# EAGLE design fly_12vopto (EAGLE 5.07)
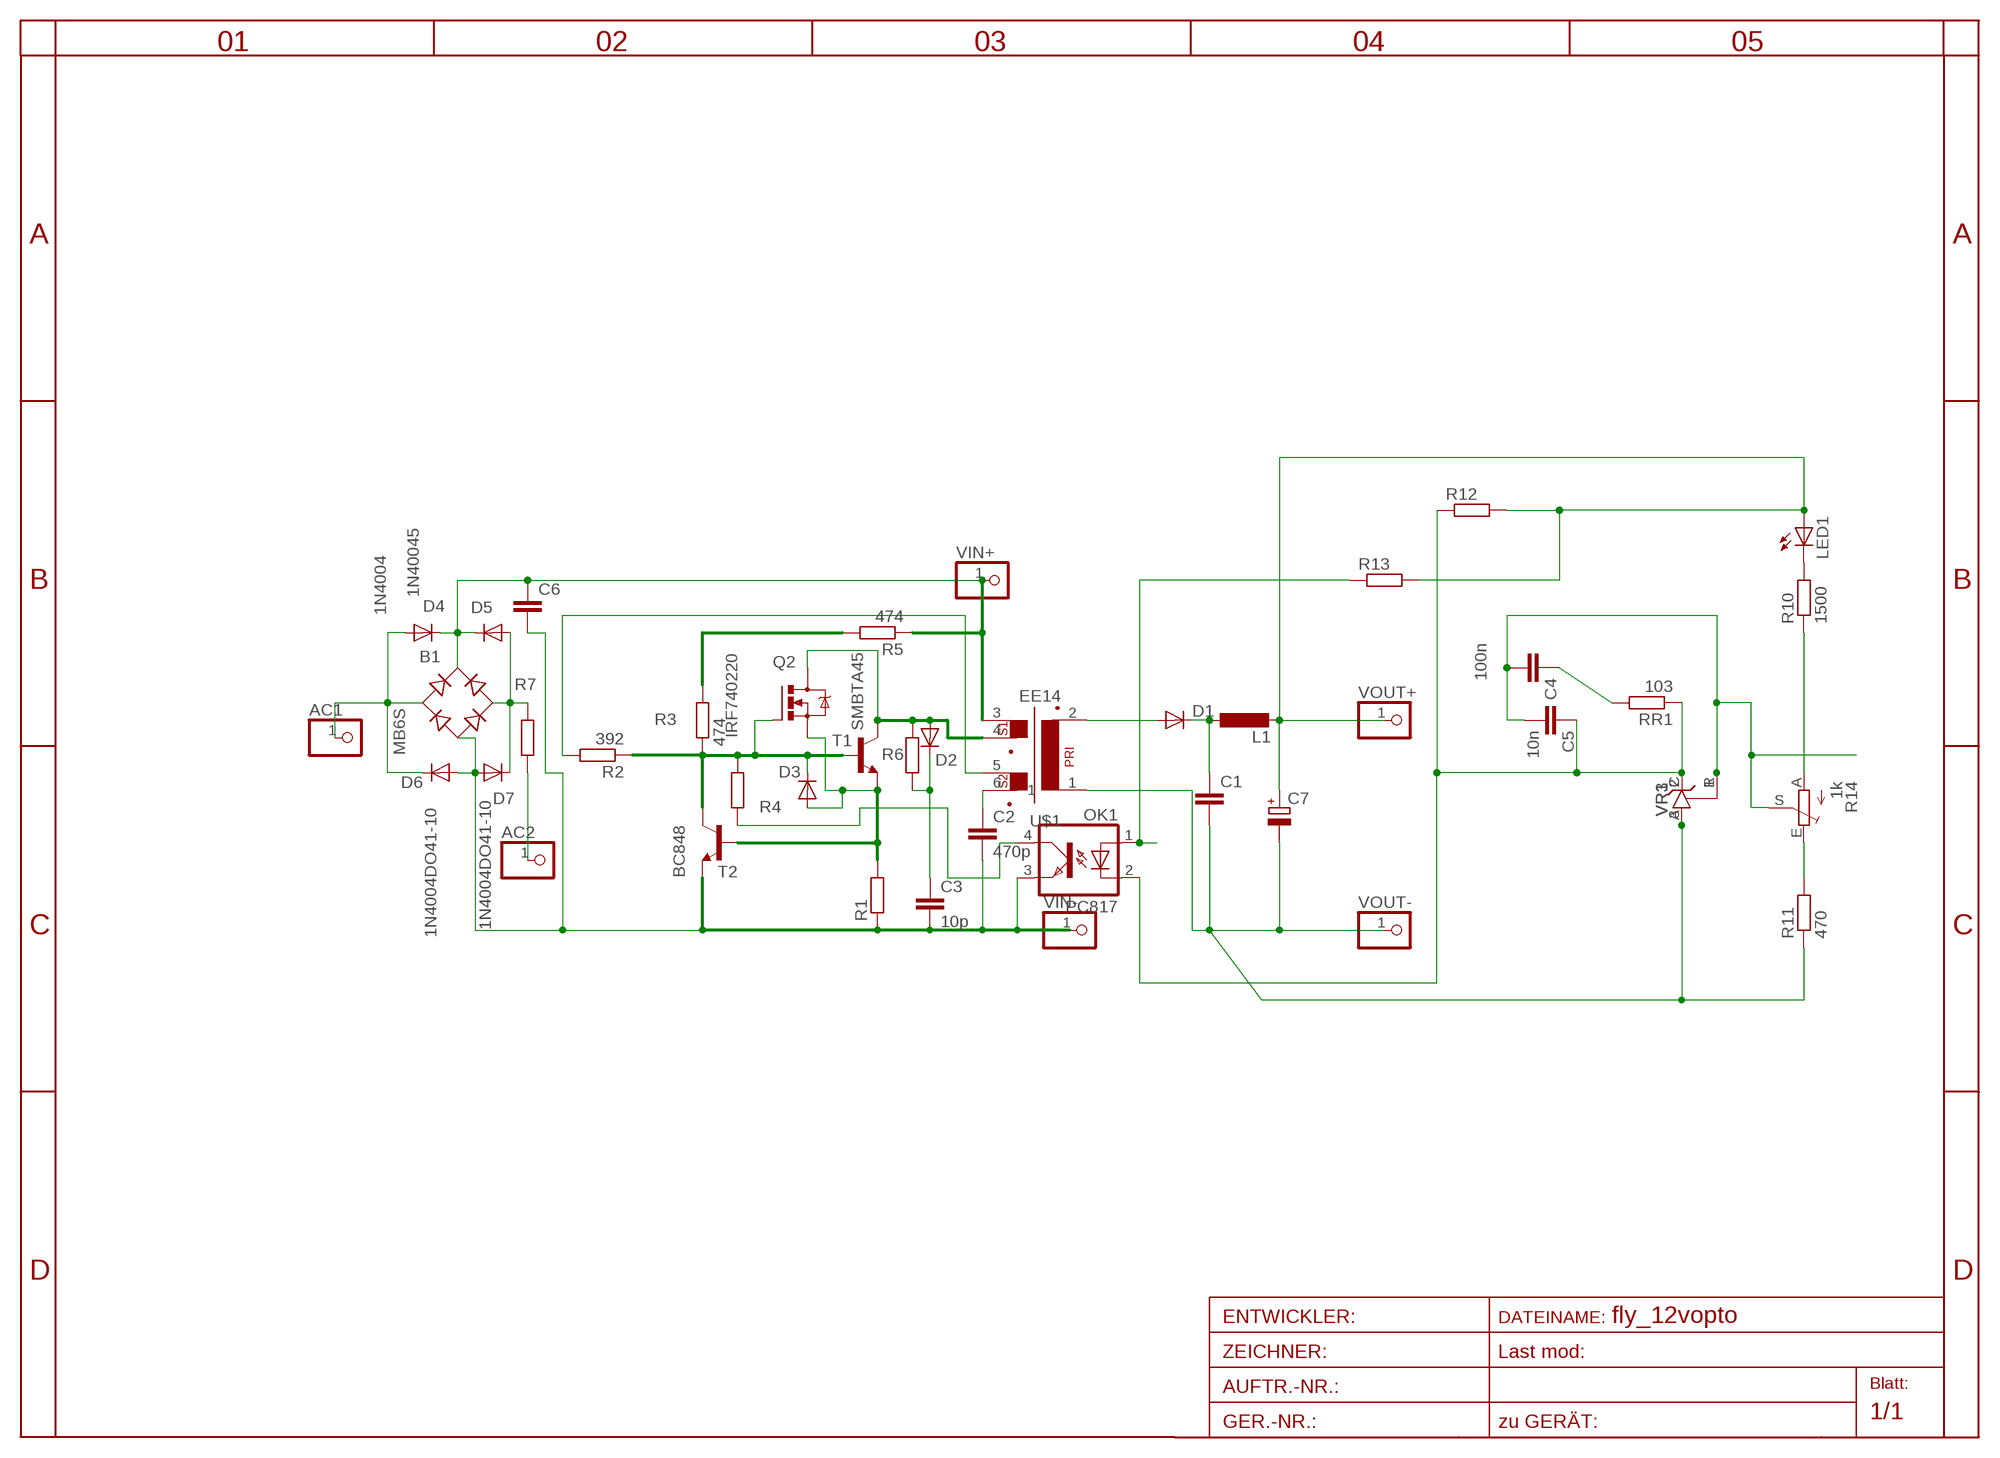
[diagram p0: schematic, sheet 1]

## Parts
AC1  PINHD-1X11MM6  [1X1MM8]
AC2  PINHD-1X11MM6  [1X1MM8]
B1  MB6S  [SOIC-4]
C1  C-EUC0805  [C0805]
C2  470p  C-EUC0805  [C0805]
C3  10p  C-EU050-025X075  [C050-025X075]
C4  100n  C-EUC0805  [C0805]
C5  10n  C-EUC0805  [C0805]
C6  C-EU050-025X075  [C050-025X075]
C7  CPOL-EUE2.5-7  [E2,5-7]
D1  DIODE-SMA-DO214  [SMA-DO214AC]
D2  DIODE-D-5  [D-5]
D3  DIODE-MINIMELF  [MINIMELF]
D4  1N4004  [D-7.5]
D5  1N40045  [C1702-05]
D6  1N4004DO41-10  [DO41-10]
D7  1N4004DO41-10  [DO41-10]
L1  L-EU0204V  [0204V]
LED1  LED3MM  [LED3MM]
OK1  PC817  [DIL04]
Q2  IRF740220  [TO220BV]
R1  R-EU_0204/3  [0204/3]
R2  392  R-EU_R0805  [R0805]
R3  474  R-EU_R1206  [R1206]
R4  R-EU_R0805  [R0805]
R5  474  R-EU_R1206  [R1206]
R6  R-EU_0204/5  [0204/5]
R7  R-EU_0204/3  [0204/3]
R10  1500  R-EU_R0805  [R0805]
R11  470  R-EU_R1206  [R1206]
R12  R-EU_R0805  [R0805]
R13  R-EU_R0805  [R0805]
R14  1k  TRIM_EU-S64W  [S64W]
RR1  103  R-EU_R0805  [R0805]
T1  SMBTA45  BC848  [SOT23]
T2  BC848  [SOT23]
U$1  EE14  EE14EE20G  [EE20GREEN]
VIN+  PINHD-1X11MM6  [1X1MM8]
VIN-  PINHD-1X11MM6  [1X1MM8]
VOUT+  PINHD-1X11MM6  [1X1MM8]
VOUT-  PINHD-1X11MM6  [1X1MM8]
VR1  TL431CLPSOT23  [SOT23]
VR3  TL431CLPTO  [TO92-CLP]

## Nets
A: R10.1 R14.A
AC1: AC1.1 B1.~1(AC1) D4.A D6.C
AC2: AC2.1 R7.1
AC3: B1.~2(AC2) D5.A D7.C R7.2
B1C2: D3.C Q2.G R2.1 R3.1 R4.2 T1.B T2.C
C1: D2.A Q2.D R6.2 T1.C U$1.4
E: R11.2 R14.E
EB: D3.A Q2.S R1.2 T1.E T2.B
K9: C1.1 D1.K(C) L1.1
L3DOT: D1.A U$1.2
N$1: R3.2 R5.2
N$2: R2.2 U$1.5
N$3: C2.1 U$1.6
N$4: LED1.K(C) R10.2
N$5: OK1.4(COL) R4.1
N$6: C3.1 D2.C R6.1
N$7: C5.1 OK1.2(C) R12.1 RR1.1 VR1.2(C) VR3.C
N$8: OK1.1(A) R13.1
N$13: C4.1 RR1.2
OUTMINUS: C1.2 C7.- R11.1 U$1.1 VOUT-.1 VR1.3(A) VR3.A
S: C4.2 C5.2 R14.S VR1.1(R) VR3.R
V+: B1.+ C6.1 D4.C D5.C R5.1 U$1.3 VIN+.1
V-: B1.- C2.2 C3.2 C6.2 D6.A D7.A OK1.3(EMIT) R1.1 T2.E VIN-.1
VOUT+: C7.+ L1.2 LED1.A R12.2 R13.2 VOUT+.1

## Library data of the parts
AC1 AC2 VIN+ VIN- VOUT+ VOUT- = pinhead:PINHD-1X1: PIN HEADER
B1 = rectifier:MB*S: Bridge Rectifier Source: http://www.fairchildsemi.com/ds/MB/MB6S.pdf
C1-C6 = rcl:C-EU: CAPACITOR, European symbol
C7 = rcl:CPOL-EU: POLARIZED CAPACITOR, European symbol
D1-D3 = diode:DIODE-: DIODE
D4-D7 = diode:1N4004: DIODE
L1 = rcl:L-EU: INDUCTOR, European symbol
LED1 = led:LED: LED
OK1 = optocoupler:PC817: SHARP OPTO COUPLER
Q2 = transistor-power:IRF740: N-CHANNEL MOS FET
R1-R7 R10-R13 RR1 = rcl:R-EU_: RESISTOR, European symbol
R14 = pot:TRIM_EU-: POTENTIOMETER
T1 T2 = transistor:BC848: NPN TRANSISTOR
U$1 = trafo:EE14
VR1 VR3 = v-reg:TL431CLP: VOLTAGE REGULATOR

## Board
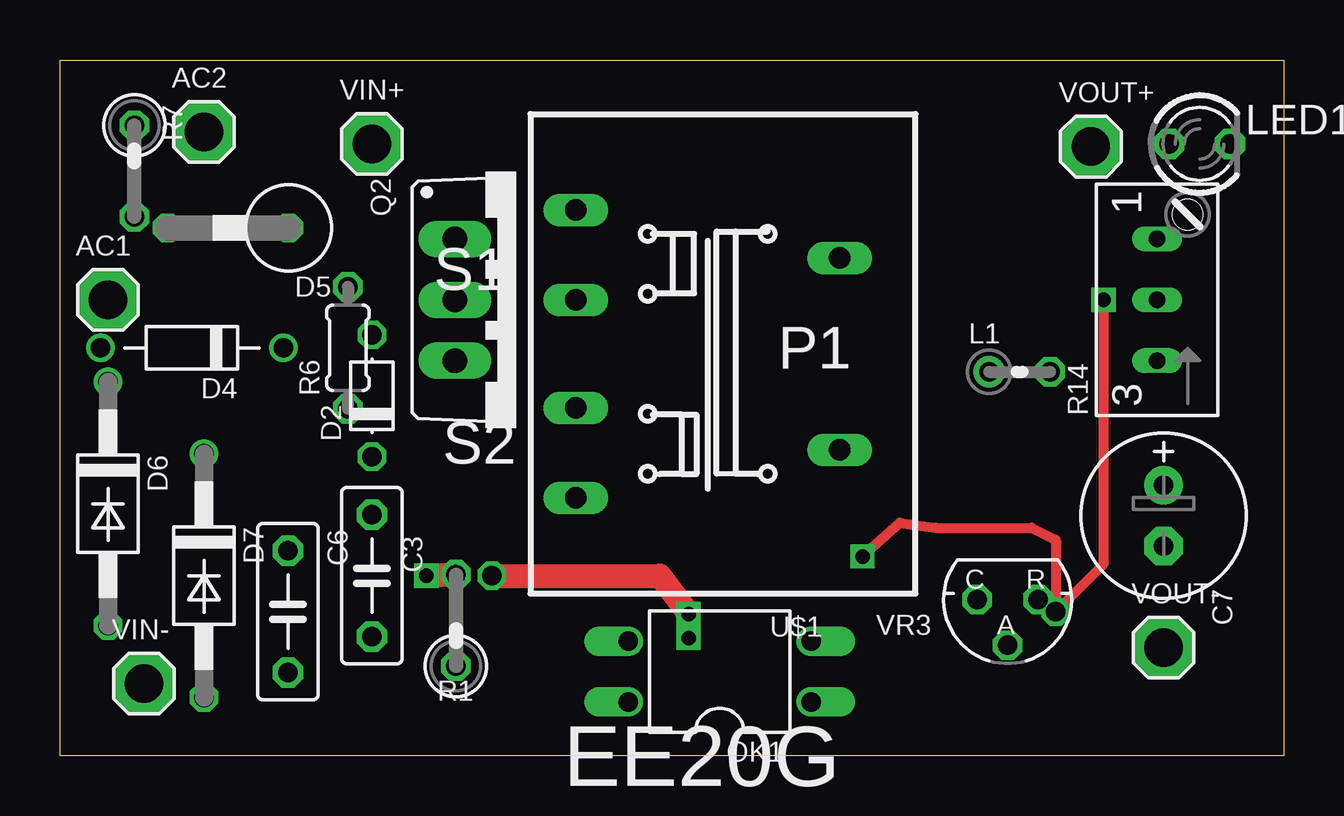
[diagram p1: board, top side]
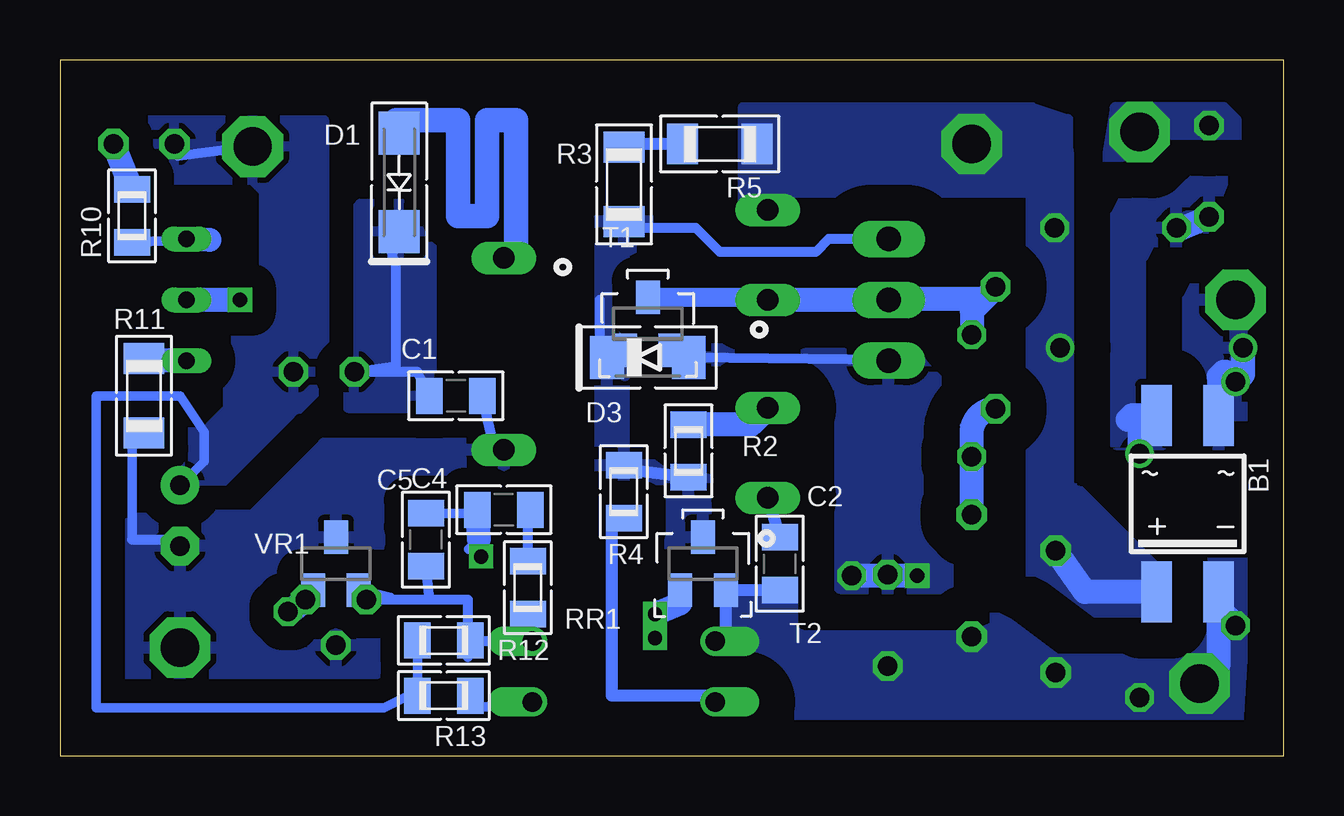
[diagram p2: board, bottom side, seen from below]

Size 51 x 29 mm. Coordinates in mm from the lower left corner, seen from the top.
Outline: 0,29 51,29 51,0 0,0 0,29
Copper layers (1*16): Top 0.035mm / dielectric 1.5mm / Bottom 0.035mm
Design rules "default *": minimum track width 10mil, minimum drill 20mil, track to track 8mil, track to pad 8mil, pad to pad 8mil, via to via 8mil, smd to smd 8mil, copper to edge 40mil, drill to drill 8mil, minimum pad ring 5mil, minimum via ring 8mil, stop-mask expansion 4mil, vias tented up to drill 0mil, thermal gap 10mil

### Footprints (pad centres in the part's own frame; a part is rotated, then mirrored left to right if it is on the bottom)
1X1MM8 = drill 1.6 pad 2.54 octagon: 1 0,0
SOIC-4 = smd 1.27 x 2.54: + 1.3,3.685; - -1.3,3.685; ~1 -1.3,-3.685; ~2 1.3,-3.685
C0805 = smd 1.1 x 1.5: 1 -1.1,0; 2 1.1,0
C050-025X075 = drill 0.8 pad 1.27 octagon: 1 -2.54,0; 2 2.54,0
E2,5-7 = drill 0.813 pad 1.6 round: + -1.27,0 | drill 0.813 pad 1.6 octagon: - 1.27,0
SMA-DO214AC = smd 1.8 x 1.7: A 2.05,-0.127; K -2.05,-0.127
D-5 = drill 0.8 octagon: A 2.54,0; C -2.54,0
MINIMELF = smd 1.4 x 1.8: A 1.7,0; C -1.7,0
D-7.5 = drill 0.8 round: A 3.81,0; C -3.81,0
C1702-05 = drill 0.8 octagon: A 2.54,0; C -2.54,0
DO41-10 = drill 0.8 octagon: A 5.08,0 | drill 0.8 round: C -5.08,0
0204V = drill 0.813 octagon: 1 -1.27,0; 2 1.27,0
LED3MM = drill 0.8 pad 1.27 octagon: A -1.27,0; K 1.27,0
DIL04 = drill 0.813 offset: 1 -1.27,-3.81; 2 1.27,-3.81; 3 1.27,3.81; 4 -1.27,3.81
TO220BV = drill 1.016 long: D 0,-2.54; G -2.54,-2.54; S 2.54,-2.54
0204/3 = drill 0.813 octagon: 1 -1.27,0; 2 2.54,0
R0805 = smd 1.1 x 1.5: 1 -1.1,0; 2 1.1,0
R1206 = smd 1.3 x 1.7: 1 -1.55,0; 2 1.55,0
0204/5 = drill 0.813 octagon: 1 -2.54,0; 2 2.54,0
S64W = drill 0.7 long: A 2.54,1.27; E -2.54,1.27; S 0,1.27
SOT23 = smd 1 x 1.4: B -0.95,-1.1; C 0,1.1; E 0.95,-1.1
EE20GREEN = drill 0.9 pad 1.2 long: 1 5.5,-4; 2 5.5,4; 3 -5.5,6; 4 -5.5,2.25; 5 -5.5,-2.25; 6 -5.5,-6
SOT23' = smd 1 x 1.4: 1 -0.95,-1.1; 2 0.95,-1.1; 3 0,1.1
TO92-CLP = drill 0.813 octagon: A 0,1.905; C 1.27,0; R -1.27,0

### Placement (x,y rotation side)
AC1  2,19 0 top
AC2  6,26 0 top
B1  4,10.5 180 bottom
C1  34.5,15 0 bottom
C2  21,8 270 bottom
C3  13,7.5 270 top
C4  32.5,10.25 180 bottom
C5  35.75,9 90 bottom
C6  9.5,6 270 top
C7  46,10 270 top
D1  36.99,23.89 90 bottom
D2  13,15 90 top
D3  26.5,16.6 0 bottom
D4  5.5,17 180 top
D5  7,22 180 top
D6  2,10.5 270 top
D7  6,7.5 270 top
L1  40,16 0 top
LED1  47.5,25.5 0 top
OK1  27.5,3.5 90 top
Q2  19,19 270 top
R1  16.5,5 90 top
R2  24.8,12.7 90 bottom
R3  27.49,23.81 90 bottom
R4  27.5,11 90 bottom
R5  23.5,25.5 180 bottom
R6  12,17 90 top
R7  3.1,25 270 top
R10  48,22.5 90 bottom
R11  47.5,15 90 bottom
R12  35,4.8 180 bottom
R13  35,2.5 180 bottom
R14  47,19 90 top
RR1  31.5,7 90 bottom
T1  26.5,18 0 bottom
T2  24.2,8 0 bottom
U$1  27,16.75 0 top
VIN+  13,25.5 0 top
VIN-  3.5,3 0 top
VOUT+  42.97,25.39 0 top
VOUT-  46,4.5 0 top
VR1  [SOT23']  39.5,8 0 bottom
VR3  39.5,6.5 180 top

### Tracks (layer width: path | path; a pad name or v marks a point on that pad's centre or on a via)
A
  Bottom 0.406: 44.77,21.5 R10.1
  Bottom 1: 44.77,21.5 R14.A
AC1
  Bottom 1: D4.A 1.69,15.89 D6.C 2.42,16 2.5,16 2.7,15.8 B1.~1
  pour Bottom (isolate 1.5): 1.5,20 3.5,20 4,19 4,13 1.5,13
AC2
  pour Bottom (isolate 1.5, rank 3, no thermals): 7.5,24 2.5,24 2,24.5 2,26.5 2.5,27 7,27
AC3
  Bottom 1: 6,14.19 B1.~2 | 6,14.19 6.31,14.19 6.5,14 | D5.A 4.23,22 R7.2 | D7.C 6,14.19
  pour Bottom (isolate 1.5, rank 2): 4.5,13.5 3.5,21.5 2.5,24 6,24 6.5,23.5 7,22.5 7,13 5,13
B1C2
  Bottom 0.406: Q2.G 18.96,21.54 19.5,21 23.5,21 24.5,22 27.23,22 R3.1 | D3.C 27.8,16.9 T1.B 28.4,16.9 28.5,17 28.5,19
  Bottom 0.5: R2.1 27.3,11.9 R4.2
  pour Bottom (isolate 1): 26.5,22.5 28.5,22.5 28.5,11 26,8.5 24.5,8.5 24,9 24,11.5 25.5,11.5 27.5,13 27.5,21 26.5,21.5
C1
  Bottom 0.5: U$1.4 21.6,19.1
  Bottom 0.8: 21.6,19.1 T1.C
  Bottom 1: U$1.4 Q2.D 16.42,19.04 12.5,19.04 | R6.2 12.5,19.04 | D2.A 13,18.54 12.5,19.04
E
  Bottom 0.406: 47.14,16.46 R11.2
  Bottom 1: R14.E 47.14,16.46
EB  (via drill 0.6, 0.8)
  Top 1: v26.2,5.9 25,7.5 v18,7.5 | R1.2 v15.27,7.5
  Bottom 0.4: v26.2,5.9 v26.2,4.9
  Bottom 0.406: T1.E 25.2,16.9 D3.A 16.5,16.5 Q2.S
  Bottom 1: T2.B 25.15,6.35 v26.2,5.9 | v15.27,7.5 v18,7.5
  pour Bottom (isolate 1.5): 14,7 14,16 15.5,17.5 26.5,17.5 26.5,15 18.5,15.5 18.5,7
K9
  Bottom 0.406: D1.K 37.16,20.84 37,20.5 37,16.23 L1.1 36.1,16 C1.1
  pour Bottom (isolate 1, rank 3): 35.5,23 38.5,23 39,22.5 39,14.5 35.5,14.5
L3DOT
  Bottom 1.016: U$1.2 32,20.75 32,26.5 33.2,26.5 33.2,22.5 34.4,22.5 34.4,26.5 37,26.5 arc90 36.86,26.36 D1.A
N$1
  Bottom 0.5: R5.2 27.35,25.5 R3.2
N$2
  Bottom 0.5: U$1.5 22.1,14.5
  Bottom 1: R2.2 22.2,13.8 U$1.5
N$3
  Bottom 0.5: C2.1 U$1.6
N$4
  Bottom 1: R10.2 LED1.K
N$5
  Bottom 0.5: R4.1 28,9.9 28,2.5 23.96,2.5 OK1.4
N$6
  Bottom 1: R6.1 arc-90 13,13.46 D2.C C3.1
N$7
  Bottom 0.406: RR1.1 31.31,6.21 OK1.2 33.73,4.77 34,4.5 | VR1.2 37.23,6.58 VR3.C 35.6,6.5 | 34,4.5 34,4.1 R12.1 | 34,4.5 34,6.5 35.6,6.5 | 35.6,6.5 C5.1
N$8
  Bottom 0.406: R13.1 33.54,2 OK1.1
N$13
  Bottom 0.406: RR1.2 31.5,9.9 C4.1
OUTMINUS
  Bottom 0.4: 48,9 48,13.5 47.55,13.5 R11.1
  Bottom 0.406: C1.2 33,13.25 U$1.1 | 48,9 46.27,9 C7.-
  pour Bottom (isolate 1): 32,13 40,13 43,10 47.5,10 48.5,9.5 48.5,2 48,1.5 33.5,1.5 33.5,9 32,11
S  (via drill 0.6, 0.8)
  Top 0.406: v43.5,19 43.5,8 v41.5,6 41.5,9 40.5,9.5 36.5,9.5 35,9.7 v33.45,8.3
  Bottom 0.4: C5.2 33.75,10.1 C4.2
  Bottom 0.406: v33.45,8.3 33.53,9.03 33.97,8.6
  Bottom 1: v43.5,19 R14.S | 33.53,9.03 C4.2 | v41.5,6 VR3.R 41.27,6.08 VR1.1
V+
  Bottom 1: B1.+ 8.28,6.82 C6.1
  pour Bottom (isolate 1.5, rank 3, no thermals): 22.5,22.5 22.5,27 10.5,27 9,26.5 9,11.5 5.5,8 5.5,5.5 10,5.5 10.5,6 10.5,23.5 20.5,23.5 21,23
V-
  Bottom 0.5: OK1.3 23.42,4.5 23,4.5 23.25,4.75 T2.E C2.2
  Bottom 1: VIN-.1 2.7,3.8 B1.- 2.7,6.12 D6.A
  pour Bottom (isolate 1.5, rank 2, no thermals): 1.5,8 4,8 4.5,7.5 4.5,5 5.5,4 9.5,4 11.5,5.5 12.5,6 15.5,6 25,8 25,2.5 24.5,0 2,0
VOUT+
  Bottom 0.4: C7.+ 45,12.27 45,13.5 46,15 49.5,15 49.5,2 37.5,2 36.5,2.5 R13.2 R12.2
  Bottom 0.406: L1.2 41.5,15.73 | VOUT+.1 46.08,25
  pour Bottom (isolate 1, rank 2): 49,26.5 40,26.5 40,15.5 45.5,10 47,10 48,11 48,13.5 45,13.5 44,14.5 44,18.5 42.5,20 42.5,23.5 43,24 49,24 49.5,23.5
